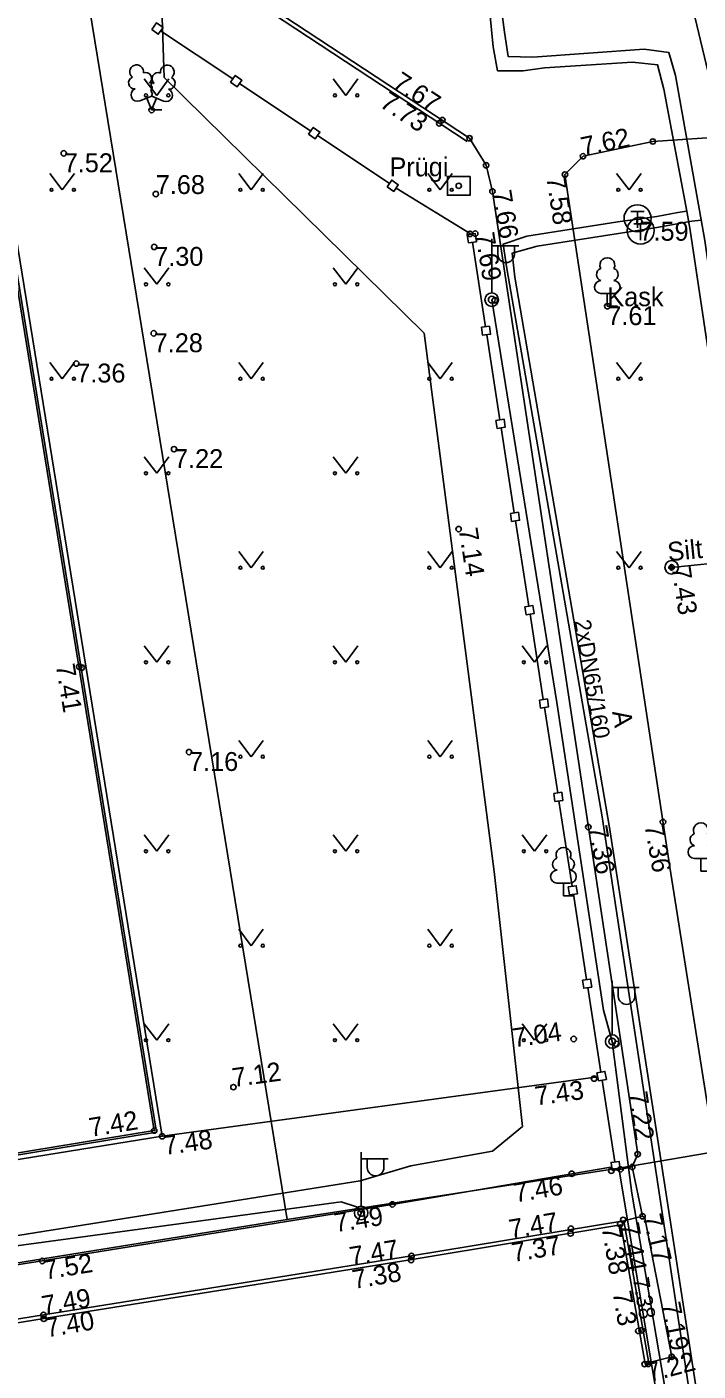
# Model space of a CAD drawing. Extents: x 473307 to 473719, y 6532843 to 6533381.
# Drawn here: x 473608.96 to 473633.83, y 6533058.21 to 6533108 of the extents above; entities that cross this region are included whole.
import ezdxf

# ---------------------------------------------------------------- set-up
doc = ezdxf.new("R2010")
doc.units = 0
for name, color, linetype in [('AED', 7, 'Continuous'), ('Default', 7, 'Continuous'), ('HALJASTUS', 7, 'Continuous'), ('KORGUS', 7, 'Continuous'), ('KPKAABEL', 7, 'Continuous'), ('LIIKLUS', 7, 'Continuous'), ('MPKAABEL', 7, 'Continuous'), ('PIIR', 7, 'Continuous'), ('POST', 7, 'Continuous'), ('PUU', 7, 'Continuous'), ('RAJATIS', 7, 'Continuous'), ('TEE', 7, 'Continuous'), ('TKAEV', 7, 'Continuous'), ('TTRASS', 7, 'Continuous'), ('TTRASS_TEKST', 7, 'Continuous')]:
    doc.layers.add(name, color=color, linetype=linetype)

# ---------------------------------------------------------------- blocks, each defined once
blk = doc.blocks.new('LEHTP1')
at = {"layer": 'Default'}
for p, q in [((0.48, 0.95), (-0.48, 0.95)), ((0, 0), (0, 0.95)), ((0.76, 0), (0, 0))]:
    blk.add_line(p, q, dxfattribs=at)
for centre, radius, start, end in [((0, 3.04), 0.554, 332.5799, 207.4201), ((-0.34, 2.345), 0.465, 109.02174, 253.14154), ((0.34, 2.345), 0.465, 286.85082, 70.98591), ((-0.475, 1.425), 0.475, 90.0016, 269.3953), ((0.475, 1.425), 0.475, 270.6047, 89.9984)]:
    blk.add_arc(centre, radius, start, end, dxfattribs=at)
blk = doc.blocks.new('SOKAEV')
at = {"layer": 'Default'}
for p, q in [((-0.5, 0.5), (0.5, 0.5)), ((0, -0.7), (0, 0.5))]:
    blk.add_line(p, q, dxfattribs=at)
blk.add_circle((0, 0), 1, dxfattribs=at)
blk = doc.blocks.new('LIIKLP')
at = {"layer": 'Default'}
for radius in [0.5, 0.1]:
    blk.add_circle((0, 0), radius, dxfattribs=at)
blk = doc.blocks.new('MEPOST')
at = {"layer": 'Default'}
blk.add_circle((0, 0), 0.5, dxfattribs=at)
for start, end in [(0, 180), (180, 0)]:
    blk.add_arc((0, 0), 0.25, start, end, dxfattribs=at)
blk = doc.blocks.new('VAPOST')
at = {"layer": 'Default'}
for p, q in [((0, 0.5), (0, 4.5)), ((0, 4), (2, 4)), ((0.453, 3.358), (0.453, 4)), ((1.679, 3.358), (1.679, 4))]:
    blk.add_line(p, q, dxfattribs=at)
blk.add_arc((1.066, 3.358), 0.613, 180, 0, dxfattribs=at)
blk = doc.blocks.new('MURU')
at = {"layer": 'Default'}
for p, q in [((-0.927, 1.213), (0, 0)), ((0, 0), (0.891, 1.213))]:
    blk.add_line(p, q, dxfattribs=at)
for centre in [(-0.802, 0), (0.856, 0)]:
    blk.add_circle(centre, 0.11, dxfattribs=at)
blk = doc.blocks.new('rajatm')
at = {"layer": 'Default'}
blk.add_lwpolyline([(0.843, 0.702), (-0.843, 0.702), (-0.843, -0.702), (0.843, -0.702)], close=True, dxfattribs=at)
blk = doc.blocks.new('LEHTP2')
at = {"layer": 'Default'}
for p, q in [((-0.88, 0.67), (0.01, 1.02)), ((0.01, 1.02), (0.89, 0.66)), ((0, 0), (-0.35, 0.88)), ((0, 0), (0.36, 0.88)), ((0.76, 0), (0, 0))]:
    blk.add_line(p, q, dxfattribs=at)
blk.add_lwpolyline([(0.01, 2.01), (-0.03, 1.86), (-0.03, 1.82), (-0.01, 1.76), (0.03, 1.69), (0.04, 1.65), (0.01, 1.58), (-0.04, 1.48), (-0.05, 1.43), (-0.04, 1.4), (-0.02, 1.34), (0.05, 1.22), (0.06, 1.18), (0.05, 1.14), (0.02, 1.07), (0.01, 1.02)], dxfattribs=at)
for centre, radius, start, end in [((-1.114, 2.828), 0.512, 111.50269, 232.51731), ((-1.114, 2.828), 0.512, 350.48556, 111.50017), ((1.158, 2.811), 0.512, 67.6168, 188.63142), ((1.158, 2.811), 0.512, 306.59966, 67.61428), ((-1.262, 2.005), 0.448, 111.43041, 274.49868), ((-0.445, 2.327), 0.448, 308.50412, 111.57247), ((0.008, 1.535), 0.475, 66.76552, 111.50149), ((0.481, 2.318), 0.45, 67.7016, 230.51262), ((1.293, 1.986), 0.448, 264.6183, 67.68657), ((-1.053, 1.117), 0.475, 111.50143, 291.50036), ((1.07, 1.101), 0.475, 247.61661, 67.61554)]:
    blk.add_arc(centre, radius, start, end, dxfattribs=at)

msp = doc.modelspace()

# ---------------------------------------------------------------- linework, layer by layer
at = {"layer": 'AED'}
for points in [[(473613.583, 6533107.905), (473613.755, 6533108.151), (473614.001, 6533107.978), (473613.828, 6533107.733), (473613.583, 6533107.905)], [(473616.584, 6533106.076), (473613.914, 6533107.856)], [(473616.507, 6533105.956), (473616.679, 6533106.201), (473616.925, 6533106.029), (473616.752, 6533105.784), (473616.507, 6533105.956)], [(473619.48, 6533104.145), (473616.839, 6533105.906)], [(473619.395, 6533104.031), (473619.567, 6533104.276), (473619.813, 6533104.104), (473619.64, 6533103.859), (473619.395, 6533104.031)], [(473622.384, 6533102.21), (473619.726, 6533103.981)], [(473622.303, 6533102.084), (473622.475, 6533102.329), (473622.72, 6533102.157), (473622.548, 6533101.911), (473622.303, 6533102.084)], [(473625.424, 6533100.322), (473622.634, 6533102.034)], [(473590.733, 6533098.405), (473608.387, 6533101.273), (473613.972, 6533066.906), (473577.266, 6533060.977), (473573.194, 6533086.372)], [(473625.275, 6533100.301), (473625.317, 6533100.004), (473625.614, 6533100.046), (473625.572, 6533100.343), (473625.275, 6533100.301)], [(473625.949, 6533096.895), (473625.466, 6533100.025)], [(473625.8, 6533096.874), (473625.843, 6533096.577), (473626.14, 6533096.619), (473626.097, 6533096.916), (473625.8, 6533096.874)], [(473626.484, 6533093.444), (473625.995, 6533096.599)], [(473626.339, 6533093.423), (473626.381, 6533093.126), (473626.678, 6533093.169), (473626.636, 6533093.466), (473626.339, 6533093.423)], [(473627.017, 6533090.001), (473626.53, 6533093.147)], [(473626.872, 6533089.981), (473626.915, 6533089.684), (473627.212, 6533089.726), (473627.169, 6533090.023), (473626.872, 6533089.981)], [(473627.553, 6533086.543), (473627.063, 6533089.705)], [(473627.408, 6533086.522), (473627.451, 6533086.225), (473627.748, 6533086.268), (473627.705, 6533086.565), (473627.408, 6533086.522)], [(473628.089, 6533083.084), (473627.599, 6533086.246)], [(473627.945, 6533083.064), (473627.987, 6533082.767), (473628.284, 6533082.809), (473628.242, 6533083.106), (473627.945, 6533083.064)], [(473628.626, 6533079.626), (473628.135, 6533082.788)], [(473628.481, 6533079.605), (473628.523, 6533079.308), (473628.82, 6533079.351), (473628.778, 6533079.648), (473628.481, 6533079.605)], [(473629.162, 6533076.167), (473628.672, 6533079.329)], [(473629.017, 6533076.147), (473629.059, 6533075.85), (473629.356, 6533075.892), (473629.314, 6533076.189), (473629.017, 6533076.147)], [(473629.698, 6533072.709), (473629.208, 6533075.871)], [(473629.549, 6533072.688), (473629.592, 6533072.391), (473629.889, 6533072.433), (473629.846, 6533072.73), (473629.549, 6533072.688)], [(473630.229, 6533069.281), (473629.744, 6533072.412)], [(473613.972, 6533066.906), (473630.107, 6533069.108)], [(473630.133, 6533068.96), (473630.429, 6533069.012), (473630.377, 6533069.307), (473630.081, 6533069.255), (473630.133, 6533068.96)], [(473630.745, 6533065.956), (473630.275, 6533068.985)], [(473630.645, 6533065.639), (473630.942, 6533065.681), (473630.9, 6533065.978), (473630.603, 6533065.936), (473630.645, 6533065.639)]]:
    msp.add_lwpolyline(points, dxfattribs=at)
at = {"layer": 'KORGUS'}
for centre in [(473613.58, 6533104.925), (473624.236, 6533104.428), (473624.35, 6533104.551), (473625.357, 6533103.878), (473610.323, 6533103.319), (473632.15, 6533103.757), (473625.974, 6533102.875), (473629.563, 6533103.211), (473628.895, 6533102.535), (473624.959, 6533102.115), (473626.205, 6533101.908), (473613.733, 6533101.811), (473625.375, 6533100.336), (473625.572, 6533100.343), (473631.654, 6533100.782), (473613.675, 6533099.851), (473626.295, 6533097.873), (473630.464, 6533097.656), (473613.657, 6533096.651), (473610.788, 6533095.53), (473614.41, 6533092.36), (473624.954, 6533089.4), (473632.846, 6533087.982), (473610.896, 6533084.303), (473610.994, 6533084.27), (473614.966, 6533081.139), (473632.527, 6533078.549), (473629.76, 6533078.36), (473629.217, 6533070.51), (473630.803, 6533070.325), (473629.975, 6533069.044), (473616.61, 6533068.726), (473613.678, 6533067.117), (473613.972, 6533066.906), (473631.589, 6533066.243), (473629.145, 6533065.517), (473630.61, 6533065.628), (473630.945, 6533065.681), (473631.389, 6533065.77), (473622.497, 6533064.382), (473629.115, 6533063.486), (473630.937, 6533063.648), (473631.051, 6533063.81), (473631.769, 6533063.943), (473629.101, 6533063.307), (473609.528, 6533062.286), (473623.194, 6533062.32), (473623.209, 6533062.474), (473609.571, 6533060.287), (473609.585, 6533060.144), (473631.613, 6533059.695), (473631.737, 6533059.715), (473632.849, 6533058.737), (473631.844, 6533058.464), (473631.976, 6533058.475)]:
    msp.add_circle(centre, 0.1, dxfattribs=at)
at = {"layer": 'KPKAABEL'}
msp.add_lwpolyline([(473575.894, 6533057.765), (473578.381, 6533058.268), (473592.823, 6533060.715), (473621.311, 6533065.257), (473623.181, 6533065.813), (473626.204, 6533066.359), (473627.317, 6533067.271), (473626.267, 6533076.719), (473623.676, 6533096.66), (473614.05, 6533106.128), (473613.895, 6533110.57), (473612.665, 6533115.488), (473610.79, 6533128.403), (473608.964, 6533138.127), (473603.611, 6533167.485), (473599.245, 6533215.151)], dxfattribs=at)
at = {"layer": 'LIIKLUS'}
msp.add_lwpolyline([(473632.846, 6533087.982), (473634.281, 6533088.125)], dxfattribs=at)
at = {"layer": 'MPKAABEL'}
for points in [[(473626.181, 6533097.897), (473628.591, 6533082.98), (473630.318, 6533071.578), (473630.644, 6533070.419), (473631.369, 6533064.793), (473632.97, 6533055.434)], [(473626.181, 6533097.897), (473628.591, 6533082.98), (473630.318, 6533071.578), (473630.644, 6533070.419)], [(473630.644, 6533070.419), (473631.369, 6533064.793), (473632.97, 6533055.434), (473635.763, 6533040.307)], [(473577.882, 6533057.546), (473591.171, 6533059.946), (473591.903, 6533059.383), (473592.463, 6533060.196), (473605.279, 6533062.516), (473606.217, 6533062.334), (473606.581, 6533061.971), (473606.831, 6533062.478), (473607.38, 6533062.686), (473620.605, 6533064.482), (473621.172, 6533064.297), (473621.344, 6533064.067)]]:
    msp.add_lwpolyline(points, dxfattribs=at)
at = {"layer": 'PIIR'}
msp.add_lwpolyline([(473678.608, 6532842.593), (473677.66, 6532847.73), (473668.24, 6532906.4), (473664.64, 6532927.81), (473654.16, 6532926.37), (473630.89, 6533065.72), (473641.36, 6533067.51), (473636.3, 6533097.55), (473618.8, 6533170.64), (473609.94, 6533222.84), (473601.54, 6533272.81), (473599.09, 6533295.91), (473592.3, 6533328.43), (473587.14, 6533353.72), (473584.47, 6533353.28), (473580.56, 6533374.06), (473585.23, 6533374.14), (473584.699, 6533380.885)], dxfattribs=at)
for points in [[(473383.26, 6533220.83), (473372.23, 6533259.41), (473496.37, 6533266.79), (473499.84, 6533206.38), (473559.2, 6533209.37), (473561.43, 6533165.2), (473601.75, 6533167.04), (473607.56, 6533132.38), (473611.09, 6533109.85), (473618.6, 6533063.82), (473572.63, 6533056.43), (473548.5, 6533028.91), (473478.82, 6533017), (473455.33, 6533045.76), (473432.18, 6533083.36), (473429.59, 6533087.74), (473409.64, 6533129), (473385.1, 6533214.25), (473398.68, 6533216.8), (473398.11, 6533224.3)], [(473607.56, 6533132.38), (473601.75, 6533167.04), (473618.8, 6533170.64), (473636.3, 6533097.55), (473641.36, 6533067.51), (473630.89, 6533065.72), (473618.6, 6533063.82), (473611.09, 6533109.85)], [(473486.57, 6533007.64), (473478.82, 6533017), (473548.5, 6533028.91), (473572.63, 6533056.43), (473618.6, 6533063.82), (473630.89, 6533065.72), (473654.16, 6532926.37), (473652.82, 6532924.82), (473637.7, 6532924.6), (473625.07, 6532926.73), (473607.63, 6532930.98), (473579.04, 6532941.93), (473554.34, 6532955.84), (473531.51, 6532970.21), (473509.62, 6532987.09)]]:
    msp.add_lwpolyline(points, close=True, dxfattribs=at)
at = {"layer": 'TEE'}
for points in [[(473611.833, 6533131.482), (473615.313, 6533110.308), (473625.275, 6533103.753)], [(473611.981, 6533131.506), (473615.451, 6533110.398), (473625.357, 6533103.878)], [(473641.984, 6533061.181), (473638.52, 6533086.83), (473635.417, 6533103.564), (473635.08, 6533103.954), (473632.15, 6533103.757), (473629.563, 6533103.211), (473628.895, 6533102.535)], [(473625.357, 6533103.878), (473625.974, 6533102.875), (473626.205, 6533101.908), (473631.589, 6533066.243), (473631.389, 6533065.77)], [(473628.895, 6533102.535), (473632.781, 6533076.873), (473635.574, 6533059.244), (473639.656, 6533060.104)], [(473590.775, 6533098.152), (473608.175, 6533100.978), (473613.678, 6533067.118), (473577.612, 6533061.194), (473573.187, 6533087.934), (473571.911, 6533095.138), (473590.775, 6533098.152)], [(473580.427, 6533057.568), (473587.75, 6533058.806), (473596.646, 6533060.26), (473609.528, 6533062.286), (473622.497, 6533064.382), (473629.145, 6533065.517), (473630.594, 6533065.768)], [(473630.942, 6533065.681), (473631.389, 6533065.77), (473631.769, 6533063.943), (473631.076, 6533063.778)], [(473632.017, 6533058.526), (473632.849, 6533058.737), (473631.85, 6533063.884), (473631.769, 6533063.943)]]:
    msp.add_lwpolyline(points, dxfattribs=at)
for points in [[(473590.763, 6533098.226), (473608.237, 6533101.064), (473613.764, 6533067.056), (473577.55, 6533061.107), (473573.113, 6533087.921), (473571.823, 6533095.2)], [(473596.533, 6533058.179), (473609.571, 6533060.287), (473623.209, 6533062.474), (473631.076, 6533063.778), (473631.998, 6533058.496), (473631.87, 6533058.474), (473630.97, 6533063.629), (473623.23, 6533062.346), (473609.592, 6533060.159), (473596.553, 6533058.051)]]:
    msp.add_lwpolyline(points, close=True, dxfattribs=at)
at = {"layer": 'TTRASS'}
for points in [[(473670.739, 6532903.73), (473669.823, 6532910.623), (473662.59, 6532909.156), (473646.821, 6533011.679), (473633.537, 6533100.476), (473633.406, 6533101.178), (473632.559, 6533105.696), (473632.32, 6533106.603), (473631.402, 6533106.697), (473628.136, 6533106.491), (473627.343, 6533106.38), (473626.399, 6533106.377), (473626.238, 6533107.261), (473626.052, 6533109.168), (473625.777, 6533111.724), (473625.749, 6533112.421), (473625.73, 6533112.829)], [(473671.344, 6532903.733), (473670.333, 6532911.339), (473663.087, 6532909.869), (473647.414, 6533011.77), (473634.242, 6533098.966), (473634.072, 6533100.094), (473632.984, 6533106.198), (473632.738, 6533107.055), (473631.832, 6533107.173), (473627.702, 6533106.877), (473626.788, 6533106.911), (473626.656, 6533107.813), (473626.548, 6533108.653), (473626.413, 6533111.755), (473626.375, 6533112.253)], [(473633.406, 6533101.178), (473633.081, 6533101.127), (473632.304, 6533100.979), (473630.856, 6533100.78), (473627.479, 6533100.247), (473626.609, 6533099.957), (473626.743, 6533099.051), (473630.267, 6533078.738), (473630.267, 6533078.738), (473634.025, 6533053.988), (473634.025, 6533053.988), (473609.897, 6533050.671), (473609.897, 6533050.671), (473610.826, 6533045.035)], [(473633.938, 6533100.847), (473633.59, 6533100.802), (473632.304, 6533100.574), (473630.879, 6533100.354), (473627.869, 6533099.885), (473626.941, 6533099.623), (473627.036, 6533098.737), (473630.55, 6533078.344), (473630.55, 6533078.344), (473634.37, 6533053.573), (473634.37, 6533053.573), (473610.226, 6533050.303), (473610.226, 6533050.303), (473611.111, 6533045.083)]]:
    msp.add_lwpolyline(points, dxfattribs=at)

# ---------------------------------------------------------------- block references
at = {"layer": 'HALJASTUS', "xscale": 0.5, "yscale": 0.5}
for p in [(473613.771, 6533105.467), (473620.771, 6533105.467), (473610.271, 6533101.967), (473617.271, 6533101.967), (473624.271, 6533101.967), (473631.271, 6533101.967), (473613.771, 6533098.467), (473620.771, 6533098.467), (473610.271, 6533094.967), (473617.271, 6533094.967), (473624.271, 6533094.967), (473631.271, 6533094.967), (473613.771, 6533091.467), (473620.771, 6533091.467), (473617.271, 6533087.967), (473624.271, 6533087.967), (473631.271, 6533087.967), (473613.771, 6533084.467), (473620.771, 6533084.467), (473627.771, 6533084.467), (473617.271, 6533080.967), (473624.271, 6533080.967), (473613.771, 6533077.467), (473620.771, 6533077.467), (473627.771, 6533077.467), (473617.271, 6533073.967), (473624.271, 6533073.967), (473613.771, 6533070.467), (473620.771, 6533070.467), (473627.771, 6533070.467)]:
    msp.add_blockref('MURU', p, dxfattribs=at)
at = {"layer": 'LIIKLUS', "xscale": 0.5, "yscale": 0.5}
msp.add_blockref('LIIKLP', (473632.846, 6533087.982), dxfattribs=at)
at = {"layer": 'POST', "xscale": 0.5, "yscale": 0.5}
for name, p in [('VAPOST', (473626.181, 6533097.897)), ('MEPOST', (473626.181, 6533097.897)), ('VAPOST', (473630.644, 6533070.419)), ('MEPOST', (473630.644, 6533070.419)), ('VAPOST', (473621.344, 6533064.067)), ('MEPOST', (473621.344, 6533064.067))]:
    msp.add_blockref(name, p, dxfattribs=at)
at = {"layer": 'PUU', "xscale": 0.5, "yscale": 0.5}
for name, p in [('LEHTP2', (473613.58, 6533104.925)), ('LEHTP1', (473630.464, 6533097.656)), ('LEHTP1', (473633.931, 6533076.721)), ('LEHTP1', (473628.839, 6533075.812))]:
    msp.add_blockref(name, p, dxfattribs=at)
at = {"layer": 'RAJATIS', "xscale": 0.5, "yscale": 0.5}
msp.add_blockref('rajatm', (473624.959, 6533102.115), dxfattribs=at)
at = {"layer": 'TKAEV', "xscale": 0.5, "yscale": 0.5}
for p in [(473631.583, 6533100.913), (473631.696, 6533100.458)]:
    msp.add_blockref('SOKAEV', p, dxfattribs=at)

# ---------------------------------------------------------------- texts
at = {"layer": 'KORGUS'}
for s, height, rotation, p in [('7.67', 0.7, 326.6495, (473622.457, 6533105.797)), ('7.73', 0.7, 326.6495, (473621.986, 6533105.071)), ('7.62', 0.7, 11.9177, (473629.563, 6533103.211)), ('7.58', 0.7, 278.6109, (473628.203, 6533102.43)), ('7.66', 0.7, 279.1065, (473626.205, 6533101.908)), ('7.69', 0.7, 279.1065, (473625.572, 6533100.343)), ('7.14', 0.7, 278.8114, (473624.954, 6533089.4)), ('7.43', 0.7, 278.4378, (473632.846, 6533087.982)), ('7.41', 0.7, 279.2476, (473610.026, 6533084.358)), ('7.36', 0.7, 280, (473629.76, 6533078.36)), ('7.36', 0.7, 280, (473631.838, 6533078.427)), ('7.04', 0.7, 8, (473627.005, 6533070.199)), ('7.12', 0.7, 7.7705, (473616.61, 6533068.726)), ('7.43', 0.7, 7.7705, (473627.824, 6533068.044)), ('7.22', 0.7, 278.5846, (473631.246, 6533068.517)), ('7.42', 0.7, 9.2476, (473611.319, 6533066.881)), ('7.48', 0.7, 7.7705, (473614.067, 6533066.212)), ('7.46', 0.7, 9.6886, (473627.061, 6533064.451)), ('7.49', 0.7, 8.7263, (473620.396, 6533063.351)), ('7.47', 0.7, 9.4115, (473626.879, 6533063.115)), ('7.38', 0.7, 279.9015, (473630.247, 6533063.528)), ('7.44', 0.7, 279.9015, (473630.937, 6533063.648)), ('7.17', 0.7, 283.1565, (473631.769, 6533063.943)), ('7.47', 0.7, 9.4115, (473620.973, 6533062.103)), ('7.37', 0.7, 9.4115, (473626.979, 6533062.246)), ('7.52', 0.7, 9.1805, (473609.64, 6533061.595)), ('7.38', 0.7, 9.6931, (473621.078, 6533061.248)), ('7.38', 0.6, 279.9015, (473631.403, 6533061.629)), ('7.49', 0.7, 9.6931, (473609.571, 6533060.287)), ('7.3', 0.7, 279.9015, (473630.654, 6533061.118)), ('7.19', 0.7, 280.9828, (473632.468, 6533060.7)), ('7.40', 0.7, 9.6931, (473609.703, 6533059.454)), ('7.22', 0.7, 15.1972, (473632.027, 6533057.788))]:
    msp.add_text(s, height=height, rotation=rotation, dxfattribs=at).set_placement(p)
for s, p in [('7.52', (473610.323, 6533102.619)), ('7.68', (473613.733, 6533101.811)), ('7.59', (473631.654, 6533100.082)), ('7.30', (473613.675, 6533099.151)), ('7.61', (473630.464, 6533096.956)), ('7.28', (473613.657, 6533095.951)), ('7.36', (473610.788, 6533094.83)), ('7.22', (473614.41, 6533091.66)), ('7.16', (473614.966, 6533080.439))]:
    msp.add_text(s, height=0.7, dxfattribs=at).set_placement(p)
at = {"layer": 'LIIKLUS'}
msp.add_text('Silt', height=0.7, rotation=5.6908, dxfattribs=at).set_placement((473632.728, 6533088.205))
at = {"layer": 'PUU'}
msp.add_text('Kask', height=0.7, dxfattribs=at).set_placement((473630.464, 6533097.656))
at = {"layer": 'RAJATIS'}
msp.add_text('Prügi', height=0.7, dxfattribs=at).set_placement((473622.392, 6533102.466))
at = {"layer": 'TEE'}
msp.add_text('A', height=0.7, rotation=279.4431, dxfattribs=at).set_placement((473630.639, 6533082.632))
at = {"layer": 'TTRASS_TEKST'}
msp.add_text('2xDN65/160', height=0.6, rotation=279.5559, dxfattribs=at).set_placement((473629.243, 6533085.998))

doc.saveas('drawing.dxf')
